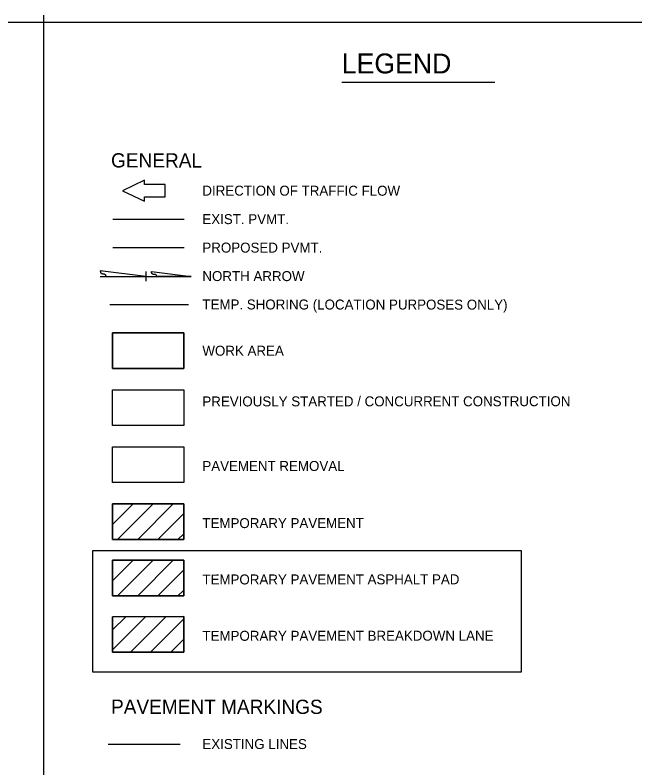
# Model space of a CAD drawing. Extents: x 2486454 to 2490507, y 369321 to 372999.
# Drawn here: x 2487627 to 2488063, y 370734 to 371263 of the extents above; entities that cross this region are included whole.
import ezdxf

# ---------------------------------------------------------------- set-up
doc = ezdxf.new("R2010")
doc.units = 0
for name, color, linetype in [('DEV BORDER CELL', 7, 'Continuous'), ('Exist Mkg Solid White Crosswalks', 7, 'Continuous'), ('Scratch_Level_3', 7, 'Continuous'), ('TC CONSTRUCTION PROPOSED ROADWAY SHADE', 7, 'Continuous'), ('TC CONSTRUCTION REMOVAL OF EXIST ASPH PVMT HATCHING', 7, 'Continuous'), ('TC CONSTRUCTION TEMP PAVEMENT ASPHALT PAD SHADE', 7, 'Continuous'), ('TC CONSTRUCTION TEMP PAVEMENT BREAKDOWN LANE SHADE', 7, 'Continuous'), ('TC CONSTRUCTION TEMP PAVEMENT FULL DEPTH SHADE', 7, 'Continuous'), ('TC CONSTRUCTION TEMP PAVEMENT HATCHING', 7, 'Continuous'), ('TC CONSTRUCTION TEMP SHORING', 7, 'Continuous'), ('TC LABEL DIRECTION OF TRAFFIC FLOW ARROW', 7, 'Continuous'), ('TC SHEET BORDER LINE THIN', 7, 'Continuous'), ('TC SHEET LAYOUT SHAPE', 7, 'Continuous'), ('TC SHEET NORTH ARROW', 7, 'Continuous'), ('TC SHEET TEXT', 7, 'Continuous')]:
    doc.layers.add(name, color=color, linetype=linetype)

msp = doc.modelspace()

# ---------------------------------------------------------------- linework, layer by layer
at = {"layer": 'DEV BORDER CELL'}
msp.add_lwpolyline([(2487745.69, 371039.87), (2487695.69, 371039.84), (2487695.7, 371014.84), (2487745.7, 371014.87)], close=True, dxfattribs=at)
at = {"layer": 'Exist Mkg Solid White Crosswalks'}
msp.add_line((2487692.58, 370751.09), (2487743.22, 370751.09), dxfattribs=at)
at = {"layer": 'Scratch_Level_3'}
msp.add_lwpolyline([(2487681.93, 370886.97), (2487982.72, 370886.97), (2487982.72, 370801.58), (2487681.93, 370801.58)], close=True, dxfattribs=at)
at = {"layer": 'TC CONSTRUCTION PROPOSED ROADWAY SHADE'}
msp.add_lwpolyline([(2487695.69, 371039.84), (2487745.69, 371039.87), (2487745.7, 371014.87), (2487695.7, 371014.84)], close=True, dxfattribs=at)
at = {"layer": 'TC CONSTRUCTION REMOVAL OF EXIST ASPH PVMT HATCHING'}
msp.add_lwpolyline([(2487695.74, 370959.83), (2487745.74, 370959.86), (2487745.76, 370934.86), (2487695.76, 370934.83)], close=True, dxfattribs=at)
at = {"layer": 'TC CONSTRUCTION TEMP PAVEMENT ASPHALT PAD SHADE'}
msp.add_lwpolyline([(2487695.77, 370855.15), (2487745.77, 370855.19), (2487745.76, 370880.19), (2487695.76, 370880.15), (2487695.77, 370855.15)], dxfattribs=at)
at = {"layer": 'TC CONSTRUCTION TEMP PAVEMENT BREAKDOWN LANE SHADE'}
msp.add_lwpolyline([(2487695.81, 370815.56), (2487745.81, 370815.59), (2487745.79, 370840.59), (2487695.79, 370840.56), (2487695.81, 370815.56)], dxfattribs=at)
at = {"layer": 'TC CONSTRUCTION TEMP PAVEMENT FULL DEPTH SHADE'}
msp.add_lwpolyline([(2487695.77, 370894.73), (2487745.77, 370894.77), (2487745.76, 370919.77), (2487695.76, 370919.73), (2487695.77, 370894.73)], dxfattribs=at)
at = {"layer": 'TC CONSTRUCTION TEMP PAVEMENT HATCHING'}
for p, q in [((2487695.76, 370919.54), (2487695.95, 370919.73)), ((2487695.77, 370905.4), (2487710.1, 370919.74)), ((2487699.24, 370894.73), (2487724.26, 370919.75)), ((2487713.39, 370894.74), (2487738.41, 370919.76)), ((2487727.54, 370894.75), (2487745.76, 370912.97)), ((2487741.69, 370894.76), (2487745.77, 370898.84)), ((2487695.76, 370879.96), (2487695.95, 370880.15)), ((2487695.77, 370865.82), (2487710.1, 370880.16)), ((2487699.24, 370855.15), (2487724.26, 370880.17)), ((2487713.39, 370855.16), (2487738.41, 370880.18)), ((2487727.54, 370855.17), (2487745.76, 370873.39)), ((2487741.69, 370855.18), (2487745.77, 370859.26)), ((2487695.8, 370831.36), (2487705, 370840.56)), ((2487695.81, 370817.22), (2487719.16, 370840.57)), ((2487708.29, 370815.57), (2487733.31, 370840.58)), ((2487722.44, 370815.58), (2487745.79, 370838.93)), ((2487736.6, 370815.59), (2487745.8, 370824.79))]:
    msp.add_line(p, q, dxfattribs=at)
at = {"layer": 'TC CONSTRUCTION TEMP SHORING'}
msp.add_line((2487693.83, 371059.81), (2487749.04, 371059.81), dxfattribs=at)
at = {"layer": 'TC LABEL DIRECTION OF TRAFFIC FLOW ARROW'}
for p, q in [((2487718.22, 371147.12), (2487702.71, 371139.81)), ((2487718.22, 371144.16), (2487718.22, 371147.12)), ((2487732.62, 371144.16), (2487718.22, 371144.16)), ((2487732.62, 371135.47), (2487732.62, 371144.16)), ((2487702.71, 371139.81), (2487718.22, 371132.51)), ((2487718.22, 371132.51), (2487718.22, 371135.47)), ((2487718.22, 371135.47), (2487732.62, 371135.47))]:
    msp.add_line(p, q, dxfattribs=at)
at = {"layer": 'TC SHEET BORDER LINE THIN'}
for p, q in [((2487647.27, 371263.19), (2487647.27, 370213.27)), ((2487856.72, 371216.12), (2487964.11, 371216.05))]:
    msp.add_line(p, q, dxfattribs=at)
for points in [[(2487695.69, 371039.84), (2487745.69, 371039.87), (2487745.7, 371014.87), (2487695.7, 371014.84)], [(2487695.74, 370999.81), (2487745.74, 370999.84), (2487745.76, 370974.84), (2487695.76, 370974.81)], [(2487695.74, 370959.83), (2487745.74, 370959.86), (2487745.76, 370934.86), (2487695.76, 370934.83)], [(2487695.76, 370919.73), (2487745.76, 370919.77), (2487745.77, 370894.77), (2487695.77, 370894.73)], [(2487695.76, 370880.15), (2487745.76, 370880.19), (2487745.77, 370855.19), (2487695.77, 370855.15)], [(2487695.79, 370840.56), (2487745.79, 370840.59), (2487745.81, 370815.59), (2487695.81, 370815.56)]]:
    msp.add_lwpolyline(points, close=True, dxfattribs=at)
at = {"layer": 'TC SHEET LAYOUT SHAPE'}
msp.add_lwpolyline([(2487016.56, 370666.84), (2487016.56, 370976.16), (2487016.56, 371248.27), (2487026.56, 371258.27), (2487469.58, 371258.27), (2487940.56, 371258.27), (2488261.56, 371258.27), (2488261.56, 371178.27), (2488346.56, 371178.27), (2488346.56, 371226.27), (2488506.56, 371226.27), (2488506.56, 370891.3), (2488506.56, 370612.1), (2488506.56, 370360.77), (2487778.38, 370360.77), (2487778.38, 370218.27), (2487608.92, 370218.27), (2487256.14, 370218.27), (2487016.56, 370218.27)], close=True, dxfattribs=at)
at = {"layer": 'TC SHEET NORTH ARROW'}
for p, q in [((2487719.04, 371079.56), (2487687.15, 371083.48)), ((2487719.04, 371082.98), (2487719.04, 371076.15)), ((2487723.09, 371082.98), (2487750.92, 371079.56)), ((2487723.09, 371082.98), (2487750.92, 371079.56)), ((2487687.15, 371079.56), (2487750.92, 371079.56)), ((2487690.92, 371079.58), (2487719.04, 371079.56)), ((2487750.92, 371079.56), (2487726.7, 371079.57)), ((2487750.92, 371079.56), (2487726.7, 371079.57))]:
    msp.add_line(p, q, dxfattribs=at)
for points in [[(2487687.15, 371083.48), (2487687.05, 371081.5), (2487690.95, 371081.43), (2487690.92, 371079.58)], [(2487726.7, 371079.56), (2487726.89, 371080.94), (2487722.99, 371081), (2487723.09, 371082.98)], [(2487726.7, 371079.56), (2487726.89, 371080.94), (2487722.99, 371081), (2487723.09, 371082.98)]]:
    msp.add_open_spline(points, degree=2, dxfattribs=at)
at = {"layer": 'TC SHEET TEXT'}
for p, q in [((2487695.88, 371119.83), (2487746.07, 371119.8)), ((2487695.87, 371099.83), (2487746.07, 371099.8))]:
    msp.add_line(p, q, dxfattribs=at)

# ---------------------------------------------------------------- texts
for s, height, rotation, p in [('LEGEND', 13.999, 359.9597, (2487856.69, 371222.21)), ('GENERAL', 10, 359.9597, (2487694.67, 371156.13)), ('DIRECTION OF TRAFFIC FLOW', 7, 359.9597, (2487758.81, 371136.37)), ('EXIST. PVMT.', 7, 359.9597, (2487758.81, 371116.34)), ('PROPOSED PVMT.', 7, 359.9597, (2487758.81, 371096.34)), ('NORTH ARROW', 7, 359.9597, (2487758.81, 371076.34)), ('TEMP. SHORING (LOCATION PURPOSES ONLY)', 7, 359.9597, (2487758.81, 371056.4)), ('WORK AREA', 7, 0.0403, (2487758.81, 371023.88)), ('PREVIOUSLY STARTED / CONCURRENT CONSTRUCTION', 7, 0.0403, (2487758.81, 370988.25)), ('PAVEMENT REMOVAL', 7, 0.0403, (2487758.81, 370942.87)), ('TEMPORARY PAVEMENT', 7, 0.0403, (2487758.81, 370902.77)), ('TEMPORARY PAVEMENT ASPHALT PAD', 7, 0.0403, (2487758.83, 370863.18)), ('TEMPORARY PAVEMENT BREAKDOWN LANE', 7, 0.0403, (2487758.85, 370823.59)), ('PAVEMENT MARKINGS', 10, 359.9597, (2487694.67, 370772.32)), ('EXISTING LINES', 7, 359.9597, (2487758.81, 370747.62))]:
    msp.add_text(s, height=height, rotation=rotation, dxfattribs=at).set_placement(p)

doc.saveas('drawing.dxf')
